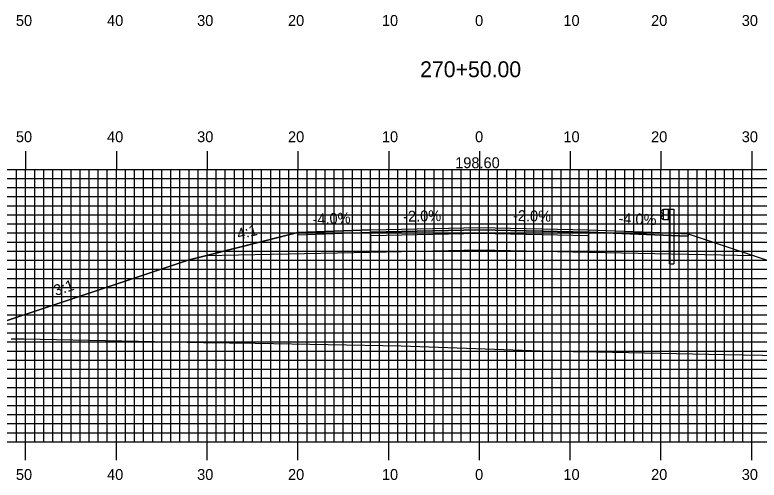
# Model space of a CAD drawing. Extents: x 1808226 to 1808569, y 442591 to 442811.
# Drawn here: x 1808340.1 to 1808422.1, y 442704.4 to 442755.7 of the extents above; entities that cross this region are included whole.
import ezdxf

# ---------------------------------------------------------------- set-up
doc = ezdxf.new("R2010")
doc.units = 0
for name, color, linetype in [('ANNOTATION', 7, 'Continuous'), ('D_Guardrail_Beam_Rt', 7, 'Continuous'), ('D_Roadway_Centerline', 7, 'Continuous'), ('D_Roadway_Centerline_Text', 7, 'Continuous'), ('D_Roadway_Edge_Shoulder', 7, 'Continuous'), ('D_Roadway_Edge_TW', 7, 'Continuous'), ('D_Roadway_Pavement', 7, 'Continuous'), ('D_Roadway_SlopeLines', 7, 'Continuous'), ('D_Roadway_SubGrade', 7, 'Continuous'), ('H_V ANNOTATION', 7, 'Continuous'), ('MAJOR', 7, 'Continuous'), ('MINOR', 7, 'Continuous'), ('S_Roadway_Centerline', 7, 'Continuous')]:
    doc.layers.add(name, color=color, linetype=linetype)

msp = doc.modelspace()

# ---------------------------------------------------------------- linework, layer by layer
at = {"layer": 'D_Guardrail_Beam_Rt'}
for p, q in [((1808411.479, 442734.18), (1808411.335, 442734.08)), ((1808411.335, 442733.937), (1808411.531, 442733.801)), ((1808411.531, 442733.602), (1808411.335, 442733.466)), ((1808411.569, 442734.202), (1808411.495, 442734.187)), ((1808411.564, 442733.737), (1808411.564, 442733.667)), ((1808411.569, 442734.285), (1808412.256, 442734.285)), ((1808411.569, 442733.118), (1808411.569, 442734.285)), ((1808412.09, 442734.285), (1808412.09, 442733.118)), ((1808412.194, 442734.285), (1808412.194, 442733.118)), ((1808412.256, 442734.285), (1808412.727, 442734.285)), ((1808412.256, 442734.285), (1808412.256, 442733.118)), ((1808412.727, 442734.285), (1808412.727, 442728.285)), ((1808411.335, 442733.323), (1808411.479, 442733.223)), ((1808411.495, 442733.216), (1808411.569, 442733.202)), ((1808412.256, 442733.118), (1808411.569, 442733.118)), ((1808412.236, 442728.285), (1808412.236, 442733.118)), ((1808412.236, 442728.285), (1808412.727, 442728.285))]:
    msp.add_line(p, q, dxfattribs=at)
for centre, major_axis, start_param, end_param in [((1808411.386, 442734.009), (-0.0877, 0), 5.323254, 7.243116), ((1808411.503, 442734.146), (-0.0417, 0), 4.907132, 5.323254), ((1808411.486, 442733.737), (0.0789, 0), 0, 0.959931), ((1808411.486, 442733.667), (0.0789, 0), 5.323254, 6.283185), ((1808411.386, 442733.395), (-0.0877, 0), 5.323254, 7.243116), ((1808411.503, 442733.257), (-0.0417, 0), 0.959931, 1.376053)]:
    msp.add_ellipse(centre, major_axis=major_axis, ratio=0.995501, start_param=start_param, end_param=end_param, dxfattribs=at)
at = {"layer": 'D_Roadway_Centerline'}
msp.add_lwpolyline([(1808333.279, 442720.029), (1808359.298, 442728.702), (1808361.124, 442729.158), (1808371.298, 442731.702), (1808379.298, 442732.022), (1808391.298, 442732.262), (1808403.298, 442732.022), (1808411.298, 442731.702), (1808414.298, 442731.582), (1808421.575, 442729.156), (1808455.49, 442717.851)], dxfattribs=at)
at = {"layer": 'D_Roadway_Edge_Shoulder'}
for points in [[(1808379.298, 442732.022), (1808371.298, 442731.702), (1808371.298, 442731.452), (1808379.298, 442731.772)], [(1808403.298, 442732.022), (1808411.298, 442731.702), (1808411.298, 442731.702), (1808414.298, 442731.582), (1808414.298, 442731.332), (1808403.298, 442731.772)]]:
    msp.add_lwpolyline(points, close=True, dxfattribs=at)
at = {"layer": 'D_Roadway_Edge_TW'}
msp.add_lwpolyline([(1808379.298, 442731.772), (1808379.298, 442732.022), (1808391.298, 442732.262), (1808403.298, 442732.022), (1808403.298, 442731.772), (1808391.298, 442732.012)], close=True, dxfattribs=at)
at = {"layer": 'D_Roadway_Pavement'}
msp.add_lwpolyline([(1808379.298, 442731.355), (1808379.298, 442731.772), (1808391.298, 442732.012), (1808403.298, 442731.772), (1808403.298, 442731.355), (1808391.298, 442731.595)], close=True, dxfattribs=at)
at = {"layer": 'D_Roadway_SlopeLines'}
for points in [[(1808371.298, 442731.702), (1808359.298, 442728.702), (1808333.279, 442720.029)], [(1808414.298, 442731.582), (1808455.49, 442717.851)]]:
    msp.add_lwpolyline(points, dxfattribs=at)
at = {"layer": 'D_Roadway_SubGrade'}
for points in [[(1808379.298, 442729.522), (1808379.298, 442731.772), (1808391.298, 442732.012), (1808403.298, 442731.772), (1808403.298, 442729.522), (1808391.298, 442729.762)], [(1808379.298, 442729.522), (1808361.124, 442729.158), (1808371.298, 442731.702), (1808371.298, 442731.452), (1808379.298, 442731.772)], [(1808403.298, 442731.772), (1808414.298, 442731.332), (1808414.298, 442731.582), (1808421.575, 442729.156), (1808403.298, 442729.522)]]:
    msp.add_lwpolyline(points, close=True, dxfattribs=at)
at = {"layer": 'MAJOR'}
for p, q in [((1808341.298, 442740.669), (1808341.298, 442738.665)), ((1808351.298, 442740.669), (1808351.298, 442738.665)), ((1808361.298, 442740.669), (1808361.298, 442738.665)), ((1808371.298, 442740.669), (1808371.298, 442738.665)), ((1808381.298, 442740.669), (1808381.298, 442738.665)), ((1808391.298, 442740.669), (1808391.298, 442738.665)), ((1808401.298, 442740.669), (1808401.298, 442738.665)), ((1808411.298, 442740.669), (1808411.298, 442738.665)), ((1808421.298, 442740.669), (1808421.298, 442738.665)), ((1808251.298, 442738.665), (1808531.298, 442738.665)), ((1808251.298, 442738.665), (1808531.298, 442738.665)), ((1808341.298, 442708.665), (1808341.298, 442738.665)), ((1808351.298, 442708.665), (1808351.298, 442738.665)), ((1808361.298, 442708.665), (1808361.298, 442738.665)), ((1808371.298, 442708.665), (1808371.298, 442738.665)), ((1808381.298, 442708.665), (1808381.298, 442738.665)), ((1808391.298, 442708.665), (1808391.298, 442738.665)), ((1808401.298, 442708.665), (1808401.298, 442738.665)), ((1808411.298, 442708.665), (1808411.298, 442738.665)), ((1808421.298, 442708.665), (1808421.298, 442738.665)), ((1808251.298, 442733.665), (1808531.298, 442733.665)), ((1808251.298, 442728.665), (1808531.298, 442728.665)), ((1808251.298, 442723.665), (1808531.298, 442723.665)), ((1808251.298, 442718.665), (1808531.298, 442718.665)), ((1808251.298, 442713.665), (1808531.298, 442713.665)), ((1808251.298, 442708.665), (1808531.298, 442708.665)), ((1808251.298, 442708.665), (1808531.298, 442708.665)), ((1808341.298, 442706.661), (1808341.298, 442708.665)), ((1808351.298, 442706.661), (1808351.298, 442708.665)), ((1808361.298, 442706.661), (1808361.298, 442708.665)), ((1808371.298, 442706.661), (1808371.298, 442708.665)), ((1808381.298, 442706.661), (1808381.298, 442708.665)), ((1808391.298, 442706.661), (1808391.298, 442708.665)), ((1808401.298, 442706.661), (1808401.298, 442708.665)), ((1808411.298, 442706.661), (1808411.298, 442708.665)), ((1808421.298, 442706.661), (1808421.298, 442708.665))]:
    msp.add_line(p, q, dxfattribs=at)
at = {"layer": 'MINOR'}
for p, q in [((1808340.298, 442708.665), (1808340.298, 442738.665)), ((1808342.298, 442708.665), (1808342.298, 442738.665)), ((1808343.298, 442708.665), (1808343.298, 442738.665)), ((1808344.298, 442708.665), (1808344.298, 442738.665)), ((1808345.298, 442708.665), (1808345.298, 442738.665)), ((1808346.298, 442708.665), (1808346.298, 442738.665)), ((1808347.298, 442708.665), (1808347.298, 442738.665)), ((1808348.298, 442708.665), (1808348.298, 442738.665)), ((1808349.298, 442708.665), (1808349.298, 442738.665)), ((1808350.298, 442708.665), (1808350.298, 442738.665)), ((1808352.298, 442708.665), (1808352.298, 442738.665)), ((1808353.298, 442708.665), (1808353.298, 442738.665)), ((1808354.298, 442708.665), (1808354.298, 442738.665)), ((1808355.298, 442708.665), (1808355.298, 442738.665)), ((1808356.298, 442708.665), (1808356.298, 442738.665)), ((1808357.298, 442708.665), (1808357.298, 442738.665)), ((1808358.298, 442708.665), (1808358.298, 442738.665)), ((1808359.298, 442708.665), (1808359.298, 442738.665)), ((1808360.298, 442708.665), (1808360.298, 442738.665)), ((1808362.298, 442708.665), (1808362.298, 442738.665)), ((1808363.298, 442708.665), (1808363.298, 442738.665)), ((1808364.298, 442708.665), (1808364.298, 442738.665)), ((1808365.298, 442708.665), (1808365.298, 442738.665)), ((1808366.298, 442708.665), (1808366.298, 442738.665)), ((1808367.298, 442708.665), (1808367.298, 442738.665)), ((1808368.298, 442708.665), (1808368.298, 442738.665)), ((1808369.298, 442708.665), (1808369.298, 442738.665)), ((1808370.298, 442708.665), (1808370.298, 442738.665)), ((1808372.298, 442708.665), (1808372.298, 442738.665)), ((1808373.298, 442708.665), (1808373.298, 442738.665)), ((1808374.298, 442708.665), (1808374.298, 442738.665)), ((1808375.298, 442708.665), (1808375.298, 442738.665)), ((1808376.298, 442708.665), (1808376.298, 442738.665)), ((1808377.298, 442708.665), (1808377.298, 442738.665)), ((1808378.298, 442708.665), (1808378.298, 442738.665)), ((1808379.298, 442708.665), (1808379.298, 442738.665)), ((1808380.298, 442708.665), (1808380.298, 442738.665)), ((1808382.298, 442708.665), (1808382.298, 442738.665)), ((1808383.298, 442708.665), (1808383.298, 442738.665)), ((1808384.298, 442708.665), (1808384.298, 442738.665)), ((1808385.298, 442708.665), (1808385.298, 442738.665)), ((1808386.298, 442708.665), (1808386.298, 442738.665)), ((1808387.298, 442708.665), (1808387.298, 442738.665)), ((1808388.298, 442708.665), (1808388.298, 442738.665)), ((1808389.298, 442708.665), (1808389.298, 442738.665)), ((1808390.298, 442708.665), (1808390.298, 442738.665)), ((1808392.298, 442708.665), (1808392.298, 442738.665)), ((1808393.298, 442708.665), (1808393.298, 442738.665)), ((1808394.298, 442708.665), (1808394.298, 442738.665)), ((1808395.298, 442708.665), (1808395.298, 442738.665)), ((1808396.298, 442708.665), (1808396.298, 442738.665)), ((1808397.298, 442708.665), (1808397.298, 442738.665)), ((1808398.298, 442708.665), (1808398.298, 442738.665)), ((1808399.298, 442708.665), (1808399.298, 442738.665)), ((1808400.298, 442708.665), (1808400.298, 442738.665)), ((1808402.298, 442708.665), (1808402.298, 442738.665)), ((1808403.298, 442708.665), (1808403.298, 442738.665)), ((1808404.298, 442708.665), (1808404.298, 442738.665)), ((1808405.298, 442708.665), (1808405.298, 442738.665)), ((1808406.298, 442708.665), (1808406.298, 442738.665)), ((1808407.298, 442708.665), (1808407.298, 442738.665)), ((1808408.298, 442708.665), (1808408.298, 442738.665)), ((1808409.298, 442708.665), (1808409.298, 442738.665)), ((1808410.298, 442708.665), (1808410.298, 442738.665)), ((1808412.298, 442708.665), (1808412.298, 442738.665)), ((1808413.298, 442708.665), (1808413.298, 442738.665)), ((1808414.298, 442708.665), (1808414.298, 442738.665)), ((1808415.298, 442708.665), (1808415.298, 442738.665)), ((1808416.298, 442708.665), (1808416.298, 442738.665)), ((1808417.298, 442708.665), (1808417.298, 442738.665)), ((1808418.298, 442708.665), (1808418.298, 442738.665)), ((1808419.298, 442708.665), (1808419.298, 442738.665)), ((1808420.298, 442708.665), (1808420.298, 442738.665)), ((1808251.298, 442737.665), (1808531.298, 442737.665)), ((1808251.298, 442736.665), (1808531.298, 442736.665)), ((1808251.298, 442735.665), (1808531.298, 442735.665)), ((1808251.298, 442734.665), (1808531.298, 442734.665)), ((1808251.298, 442732.665), (1808531.298, 442732.665)), ((1808251.298, 442731.665), (1808531.298, 442731.665)), ((1808251.298, 442730.665), (1808531.298, 442730.665)), ((1808251.298, 442729.665), (1808531.298, 442729.665)), ((1808251.298, 442727.665), (1808531.298, 442727.665)), ((1808251.298, 442726.665), (1808531.298, 442726.665)), ((1808251.298, 442725.665), (1808531.298, 442725.665)), ((1808251.298, 442724.665), (1808531.298, 442724.665)), ((1808251.298, 442722.665), (1808531.298, 442722.665)), ((1808251.298, 442721.665), (1808531.298, 442721.665)), ((1808251.298, 442720.665), (1808531.298, 442720.665)), ((1808251.298, 442719.665), (1808531.298, 442719.665)), ((1808251.298, 442717.665), (1808531.298, 442717.665)), ((1808251.298, 442716.665), (1808531.298, 442716.665)), ((1808251.298, 442715.665), (1808531.298, 442715.665)), ((1808251.298, 442714.665), (1808531.298, 442714.665)), ((1808251.298, 442712.665), (1808531.298, 442712.665)), ((1808251.298, 442711.665), (1808531.298, 442711.665)), ((1808251.298, 442710.665), (1808531.298, 442710.665)), ((1808251.298, 442709.665), (1808531.298, 442709.665))]:
    msp.add_line(p, q, dxfattribs=at)
at = {"layer": 'S_Roadway_Centerline'}
msp.add_lwpolyline([(1808339.717, 442720.004), (1808340.32, 442720.005), (1808341.083, 442719.99), (1808360.903, 442719.597), (1808366.582, 442719.512), (1808382.667, 442719.224), (1808392.949, 442718.865), (1808399.052, 442718.655), (1808404.189, 442718.587), (1808418.285, 442718.289), (1808422.497, 442718.192), (1808426.224, 442718.087), (1808444.651, 442718.059), (1808446.635, 442718.036), (1808455.658, 442717.848), (1808467.205, 442717.603), (1808469.524, 442717.615), (1808489.025, 442717.464), (1808492.329, 442717.297), (1808495.714, 442717.451), (1808509.495, 442717.537), (1808521.655, 442717.277), (1808527.344, 442717.147), (1808531.298, 442717.121)], dxfattribs=at)

# ---------------------------------------------------------------- texts
at = {"layer": 'ANNOTATION'}
for s, rotation, p in [('-4.0%', 2.29061, (1808372.93, 442732.569)), ('-2.0%', 1.14576, (1808382.904, 442732.894)), ('-2.0%', 358.85424, (1808394.984, 442732.988)), ('-4.0%', 357.70939, (1808406.59, 442732.692)), ('4:1', 14.03624, (1808364.747, 442730.925)), ('3:1', 18.43478, (1808344.627, 442724.72))]:
    msp.add_text(s, height=1.2, rotation=rotation, dxfattribs=at).set_placement(p)
at = {"layer": 'D_Roadway_Centerline'}
for s, p in [('C', (1808391.293, 442732.262)), ('L', (1808391.298, 442732.254))]:
    msp.add_text(s, height=0.0146, dxfattribs=at).set_placement(p)
at = {"layer": 'D_Roadway_Centerline_Text'}
msp.add_text('198.60', height=1.2, dxfattribs=at).set_placement((1808388.623, 442738.798))
at = {"layer": 'H_V ANNOTATION'}
for s, height, p in [('50', 1.2, (1808340.227, 442754.465)), ('40', 1.2, (1808350.27, 442754.465)), ('30', 1.2, (1808360.195, 442754.465)), ('20', 1.2, (1808370.206, 442754.465)), ('10', 1.2, (1808380.549, 442754.465)), ('0', 1.2, (1808390.816, 442754.465)), ('10', 1.2, (1808400.549, 442754.465)), ('20', 1.2, (1808410.206, 442754.465)), ('30', 1.2, (1808420.195, 442754.465)), ('270+50.00', 1.75, (1808384.759, 442748.821)), ('50', 1.2, (1808340.227, 442741.665)), ('40', 1.2, (1808350.27, 442741.665)), ('30', 1.2, (1808360.195, 442741.665)), ('20', 1.2, (1808370.206, 442741.665)), ('10', 1.2, (1808380.549, 442741.665)), ('0', 1.2, (1808390.816, 442741.665)), ('10', 1.2, (1808400.549, 442741.665)), ('20', 1.2, (1808410.206, 442741.665)), ('30', 1.2, (1808420.195, 442741.665)), ('50', 1.2, (1808340.227, 442704.465)), ('40', 1.2, (1808350.27, 442704.465)), ('30', 1.2, (1808360.195, 442704.465)), ('20', 1.2, (1808370.206, 442704.465)), ('10', 1.2, (1808380.549, 442704.465)), ('0', 1.2, (1808390.816, 442704.465)), ('10', 1.2, (1808400.549, 442704.465)), ('20', 1.2, (1808410.206, 442704.465)), ('30', 1.2, (1808420.195, 442704.465))]:
    msp.add_text(s, height=height, dxfattribs=at).set_placement(p)

doc.saveas('drawing.dxf')
